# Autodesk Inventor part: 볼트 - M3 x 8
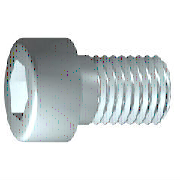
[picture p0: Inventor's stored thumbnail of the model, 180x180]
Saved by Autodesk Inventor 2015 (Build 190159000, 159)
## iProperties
IsCustomPart: 0
Created: 2012-02
Part Number: 볼트 - M3 x 8
Material: 스테인리스강
Description: 6각 소켓 머리 캡 나사
Document SubType Name: Modeling
Standard: ISO 4762
Designer: mduedu
Standard Revision: Fourth edition 2004-03-01
Standards Organization: ISO
Language: ko-KR
Size Designation: M3 x 8
Categories: <MemberInstance><Categories><Category DisplayName="조임쇠" InternalName="e4da775c-781d-43d5-af7c-5136215cf5a6" Mnemonic="FSTN"><Category DisplayName="볼트" InternalN
Density: 8.08 g/cm^3
Mass: 0.955869 g
Surface Area: 1.83001 cm^2
Volume: 0.118301 cm^3
Appearance: 반광택
Author: mduedu
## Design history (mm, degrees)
sketch "스케치1"
  geometry: L1 (-0.867, 0)-(8, 0); L2 (8, 0)-(8, 1.5); L3 (8, 1.5)-(1.25, 1.5); L4 (1.25, 1.5)-(0.943, 1.5); L5 (0.943, 1.5)-(0, 1.5); L6 (0, 1.5)-(0, 2.75); L7 (0, 2.75)-(-3, 2.75); L8 (-3, 2.75)-(-3, 1.443); L9 (-3, 1.443)-(-1.7, 1.443); L10 (-1.7, 1.443)-(-0.867, 0); L11 (-5.2, 0)-(10.2, 0) reference; L12 (0, -0.55)-(0, 3.3) reference; L13 (1.25, 1.5)-(0, 1.5)
  constraints: 22 end point, 6 parallel, 2 collinear, 2 perpendicular, 1 horizontal, 1 point on line
  dimensions: "d1" = 6.75 distance from line of L3.end L2 (= GEL); "d2" = 0.30683 distance of L4.end L3.end (computed from GAL); "d3" = 3 distance between parallel lines of L8 L6 (= KOH); "d4" = 1.3 distance of L8.end L9.end (= INTI); "d5" = 60 deg angle of L10 L1; "d6" = 3 diameter of L3 L1 (= GD); "d7" = 3 diameter of L5 L1 (= BDM); "d8" = 2.88675 diameter of L9 L1 (= 1.1547 x SW); "d9" = 5.5 diameter of L7 L1 (= KOD); "d26" = 8 distance between parallel lines of L12 L2 (= NLG)
revolve "본체" sketch "스케치1" stored, may be unused: angle "d10" = 90 deg
sketch "스케치2"
  geometry: L1 (0, -3.85)-(0, 3.85) reference; L2 (-3.85, 0)-(3.85, 0) reference; L3 (1.443, 0)-(0.722, -1.25); L4 (0.722, -1.25)-(-0.722, -1.25); L5 (-0.722, -1.25)-(-1.443, 0); L6 (-1.443, 0)-(-0.722, 1.25); L7 (-0.722, 1.25)-(0.722, 1.25); L8 (0.722, 1.25)-(1.443, 0); 2 further points
  constraints: 12 end point, 1 coincident, 1 horizontal alignment, 1 point on line, 12 other
extrude "슬롯" join sketch "스케치2" stored distance "d11" = 10; taper "d12" = 0 deg
workplane "Work Plane1"
fillet "Fillet2" dims "d30" = 0.1 (= R)
body "Solid1"
fillet "모깎기1" dims "d17" = 0.3 (= RR)
feature "스레드" dims "d13" = 6.75 (= GEL), "d14" = 0
chamfer "모따기1" distance "d15" = 0.30673 (= -0.5 x SPD + 0.5 x GD); stored, may be unused: second distance "d16" = 0.30673 (= GUL), angle "d27" = 45 deg
other parameters: "GD" = 3 [user parameter; used in 2 equation terms], "NLG" = 8 [user parameter; used in 1 equation term], "GEL" = 6.75 [user parameter; used in 2 equation terms], "KOD" = 5.5 [user parameter; used in 1 equation term], "KOH" = 3 [user parameter; used in 1 equation term], "INTI" = 1.3 [user parameter; used in 1 equation term], "GAL" = 0.30673 (= 0.61345 x PTC) [user parameter; used in 1 equation term], "GUL" = 0.30673 (= 0.61345 x PTC) [user parameter; used in 1 equation term], "BDM" = 3 (= NND) [user parameter; used in 1 equation term], "SW" = 2.5 [user parameter; used in 2 equation terms], "RR" = 0.3 [user parameter; used in 1 equation term], "SPD" = 2.38655 (= NND - 1.2269 x PTC) [user parameter; used in 1 equation term], "d19" = 0, "d28" = 0, "d29" = 0, "R" = 0.1 [user parameter; used in 1 equation term], "TOA" = 30 deg [user parameter], "GD1" = 2.38655 (= THREADDIA - 1.2269 x PTC) [user parameter], "THREADDIA" = 3 [user parameter; used in 1 equation term], "FAWI" = 45 deg [user parameter], "PTC" = 0.5 [user parameter; used in 5 equation terms], "NND" = 3 [user parameter; used in 2 equation terms], "E0" = 2.8875 (= 1.155 x SW) [user parameter]
